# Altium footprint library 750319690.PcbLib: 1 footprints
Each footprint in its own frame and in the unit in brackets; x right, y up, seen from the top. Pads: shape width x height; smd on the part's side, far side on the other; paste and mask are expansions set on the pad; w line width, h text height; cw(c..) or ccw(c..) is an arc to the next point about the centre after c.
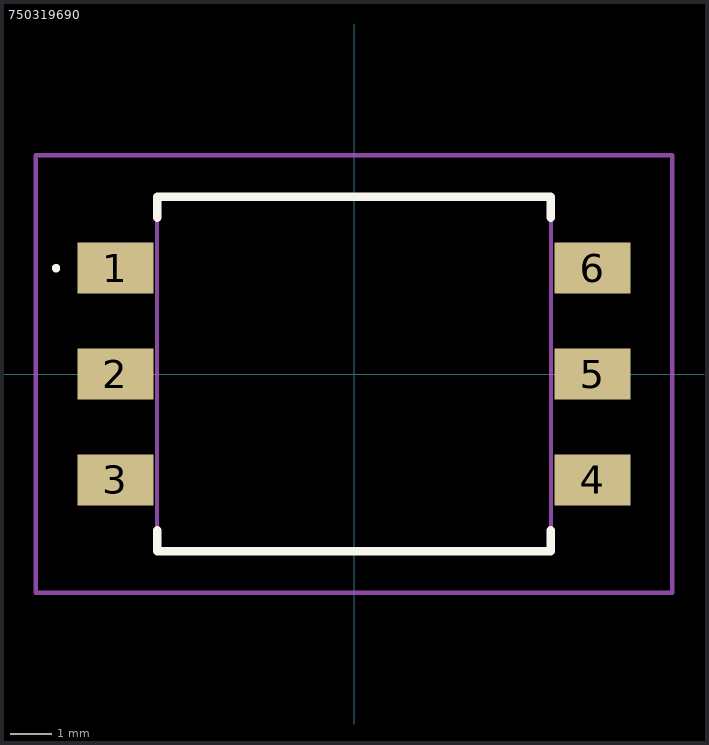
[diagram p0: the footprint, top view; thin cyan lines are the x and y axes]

## 750319690 [mm]
pads (6):
  rect 1.82x1.22 smd: 1(-5.725,2.54) 2(-5.725,0) 3(-5.725,-2.54) 4(5.725,-2.54) 5(5.725,0) 6(5.725,2.54)
Top Overlay:
  lines w0.1: -7.2,2.54 cw(c-7.15,2.54) -7.1,2.54 ; -7.2,2.54 -7.2,2.54 ; -7.2,2.54 ccw(c-7.15,2.54) -7.1,2.54 ; -7.1,2.54 -7.1,2.54
  lines w0.2: -4.725,-3.75 -4.725,-4.25 4.725,-4.25 4.725,-3.75 ; -4.725,3.75 -4.725,4.25 4.725,4.25 4.725,3.75
Mechanical 15:
  lines w0.1: -4.725,-4.25 4.725,-4.25 4.725,4.25 -4.725,4.25 -4.725,-4.25
Mechanical 20:
  lines w0.1: -7.635,-5.25 7.635,-5.25 7.635,5.25 -7.635,5.25 -7.635,-5.25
